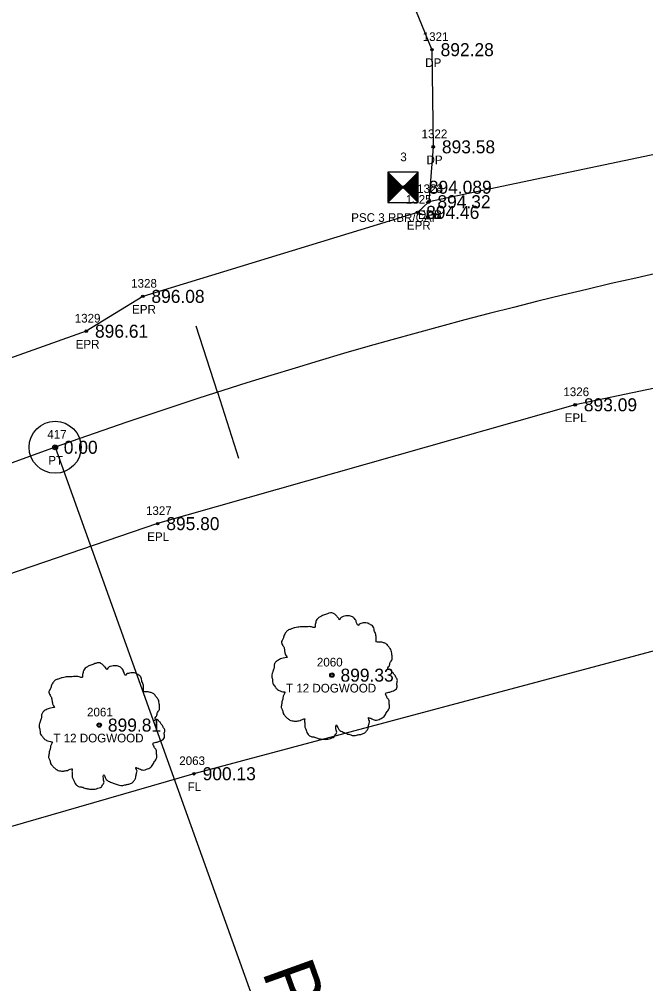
# Model space of a CAD drawing. Extents: x 1448136 to 1453623, y 1125056 to 1128842.
# Drawn here: x 1448926.9 to 1448999.1, y 1126836.9 to 1126948.2 of the extents above; entities that cross this region are included whole.
import ezdxf

# ---------------------------------------------------------------- set-up
doc = ezdxf.new("R2010")
doc.units = 0
for name, color, linetype in [('RD_EX_Driveway', 7, 'Continuous'), ('RD_EX_Driveway_txCode', 7, 'Continuous'), ('RD_EX_Fence_Other', 7, 'Continuous'), ('RD_EX_Fence_Other_txCode', 7, 'Continuous'), ('RD_EX_Road', 7, 'Continuous'), ('RD_EX_Road_txCode', 7, 'Continuous'), ('RD_EX_TX_Driveway_ELEV', 7, 'Continuous'), ('RD_EX_TX_Fence_Other_ELEV', 7, 'Continuous'), ('RD_EX_TX_Road_ELEV', 7, 'Continuous'), ('RD_EX_TX_VEG_ELEV', 7, 'Continuous'), ('RD_EX_VEG', 7, 'Continuous'), ('RD_EX_VEG_txCode', 7, 'Continuous'), ('RD_HC_Cl', 7, 'Continuous'), ('RD_HC_Data', 7, 'Continuous'), ('RD_HC_Data_Tic', 7, 'Continuous'), ('RD_HC_Survey', 7, 'Continuous'), ('RD_HC_Survey_ELEV', 7, 'Continuous'), ('RD_HC_txCode', 7, 'Continuous'), ('RD_SMD_Locator', 7, 'Continuous')]:
    doc.layers.add(name, color=color, linetype=linetype)

msp = doc.modelspace()

# ---------------------------------------------------------------- linework, layer by layer
at = {"layer": 'RD_EX_Driveway'}
msp.add_lwpolyline([(1449023.03, 1126937.4), (1449000.91, 1126949.09), (1448977.52, 1126965.39), (1448969.14, 1126957.73), (1448974.48, 1126944.7), (1448974.63, 1126933.49), (1448974.11, 1126927.16)], dxfattribs=at)
at = {"layer": 'RD_EX_Fence_Other'}
msp.add_lwpolyline([(1448975.76, 1126805.4), (1449010.37, 1126832.06), (1449003.73, 1126876.29), (1448947.02, 1126861.17), (1448899.19, 1126847.35), (1448908.83, 1126812.34)], dxfattribs=at)
at = {"layer": 'RD_EX_Road'}
for points in [[(1449482.54, 1126860.68), (1449432.31, 1126877.02), (1449388.08, 1126891.1), (1449338.36, 1126907.04), (1449288.58, 1126921), (1449240.68, 1126932.6), (1449188.86, 1126940.12), (1449140.06, 1126943.48), (1449087.15, 1126942.31), (1449035.96, 1126936.97), (1449031.74, 1126936.28), (1449027.6, 1126937.81), (1449023.03, 1126937.4), (1448974.11, 1126927.16), (1448972.81, 1126925.93), (1448941.11, 1126916.24), (1448934.6, 1126912.22), (1448888.05, 1126895.64)], [(1449474.36, 1126838.35), (1449426.72, 1126853.6), (1449379.49, 1126868.74), (1449332.07, 1126883.87), (1449284.48, 1126897.19), (1449236.53, 1126909.1), (1449187.55, 1126916.77), (1449138.32, 1126919.77), (1449088.85, 1126918.94), (1449039.71, 1126913.91), (1448991.01, 1126903.73), (1448942.83, 1126890.02), (1448896.24, 1126874.12)]]:
    msp.add_lwpolyline(points, dxfattribs=at)
at = {"layer": 'RD_EX_VEG'}
for centre, radius in [((1448962.93, 1126872.54), 0.25), ((1448962.92, 1126872.52), 0.0001), ((1448936.09, 1126866.78), 0.25), ((1448936.08, 1126866.76), 0.0001)]:
    msp.add_circle(centre, radius, dxfattribs=at)
for points in [[(1448963.06, 1126879.71), (1448962.76, 1126879.73), (1448962.44, 1126879.63), (1448962.19, 1126879.53), (1448961.96, 1126879.46), (1448961.74, 1126879.36), (1448961.44, 1126879.18), (1448961.21, 1126878.98), (1448961.09, 1126878.73), (1448961.04, 1126878.51), (1448960.99, 1126878.23), (1448960.99, 1126878.06), (1448960.86, 1126878.03), (1448960.71, 1126878.06), (1448960.46, 1126878.13), (1448960.21, 1126878.13), (1448959.96, 1126878.13), (1448959.61, 1126878.11), (1448959.26, 1126878.11), (1448958.99, 1126878.06), (1448958.66, 1126878.01), (1448958.29, 1126877.88), (1448957.94, 1126877.76), (1448957.64, 1126877.51), (1448957.39, 1126877.03), (1448957.27, 1126876.68), (1448957.12, 1126876.43), (1448957.27, 1126875.98), (1448957.44, 1126875.63), (1448957.47, 1126875.43), (1448957.54, 1126875.01), (1448957.64, 1126874.78), (1448957.77, 1126874.58), (1448957.69, 1126874.56), (1448957.32, 1126874.51), (1448957.02, 1126874.41), (1448956.59, 1126874.18), (1448956.37, 1126873.96), (1448956.27, 1126873.63), (1448956.24, 1126873.28), (1448956.14, 1126873.08), (1448956.07, 1126872.81), (1448956.04, 1126872.73), (1448955.99, 1126872.41), (1448956.09, 1126871.96), (1448956.12, 1126871.61), (1448956.24, 1126871.38), (1448956.39, 1126871.21), (1448956.57, 1126870.96), (1448956.97, 1126870.73), (1448957.29, 1126870.63), (1448957.49, 1126870.61), (1448957.32, 1126870.11), (1448957.27, 1126869.76), (1448957.14, 1126869.36), (1448957.14, 1126869.28), (1448957.09, 1126868.81), (1448957.24, 1126868.48), (1448957.32, 1126868.11), (1448957.49, 1126867.89), (1448957.77, 1126867.59), (1448958.09, 1126867.36), (1448958.59, 1126867.24), (1448958.99, 1126867.26), (1448959.56, 1126867.44), (1448959.81, 1126867.51), (1448959.79, 1126867.34), (1448959.81, 1126866.96), (1448959.81, 1126866.54), (1448959.96, 1126866.21), (1448960.06, 1126865.94), (1448960.21, 1126865.69), (1448960.54, 1126865.46), (1448960.94, 1126865.39), (1448961.36, 1126865.24), (1448961.81, 1126865.16), (1448962.31, 1126865.14), (1448962.91, 1126865.29), (1448963.19, 1126865.41), (1448963.29, 1126865.59), (1448963.49, 1126865.96), (1448963.44, 1126866.19), (1448963.46, 1126866.79), (1448963.56, 1126866.61), (1448963.74, 1126866.26), (1448964.24, 1126865.96), (1448964.64, 1126865.79), (1448965.11, 1126865.64), (1448965.41, 1126865.56), (1448965.89, 1126865.64), (1448966.26, 1126865.71), (1448966.64, 1126865.84), (1448966.94, 1126866.11), (1448967.11, 1126866.39), (1448967.16, 1126866.66), (1448967.24, 1126867.04), (1448967.29, 1126867.21)], [(1448967.29, 1126867.21), (1448967.21, 1126867.39), (1448967.16, 1126867.64), (1448967.24, 1126867.61), (1448967.41, 1126867.56), (1448967.69, 1126867.44), (1448967.91, 1126867.36), (1448968.24, 1126867.39), (1448968.51, 1126867.49), (1448968.96, 1126867.76), (1448969.24, 1126868.24), (1448969.51, 1126868.63), (1448969.59, 1126868.96), (1448969.54, 1126869.18), (1448969.51, 1126869.68), (1448969.31, 1126869.93), (1448969.26, 1126870.06), (1448969.16, 1126870.46), (1448969.24, 1126870.51), (1448969.51, 1126870.56), (1448969.89, 1126870.68), (1448970.16, 1126870.81), (1448970.38, 1126870.98), (1448970.46, 1126871.21), (1448970.43, 1126871.61), (1448970.48, 1126872.01), (1448970.41, 1126872.16), (1448970.31, 1126872.31), (1448970.23, 1126872.51), (1448970.08, 1126872.66), (1448969.99, 1126872.81), (1448969.89, 1126872.91), (1448969.76, 1126873.06), (1448969.59, 1126873.18), (1448969.44, 1126873.23), (1448969.39, 1126873.38), (1448969.54, 1126873.58), (1448969.59, 1126873.68), (1448969.61, 1126873.91), (1448969.84, 1126874.26), (1448969.89, 1126874.66), (1448969.84, 1126875.08), (1448969.79, 1126875.36), (1448969.64, 1126875.63), (1448969.44, 1126875.88), (1448969.31, 1126876.06), (1448969.14, 1126876.18), (1448968.81, 1126876.31), (1448968.56, 1126876.36), (1448968.21, 1126876.36), (1448968.01, 1126876.41), (1448968.04, 1126876.46), (1448968.04, 1126876.61), (1448968.04, 1126876.88), (1448967.96, 1126877.33), (1448967.81, 1126877.83), (1448967.81, 1126877.86), (1448967.71, 1126878.11), (1448967.49, 1126878.31), (1448967.31, 1126878.41), (1448967.11, 1126878.53), (1448966.86, 1126878.56), (1448966.56, 1126878.56), (1448966.29, 1126878.51), (1448966.09, 1126878.41), (1448965.91, 1126878.28), (1448965.84, 1126878.43), (1448965.74, 1126878.73), (1448965.69, 1126878.88), (1448965.54, 1126879.06), (1448965.31, 1126879.26), (1448964.86, 1126879.38), (1448964.24, 1126879.31), (1448963.94, 1126879.11), (1448963.79, 1126878.93), (1448963.74, 1126879.06), (1448963.54, 1126879.26), (1448963.44, 1126879.43), (1448963.26, 1126879.56), (1448963.11, 1126879.66), (1448963.01, 1126879.71)], [(1448936.23, 1126873.95), (1448935.93, 1126873.97), (1448935.6, 1126873.87), (1448935.35, 1126873.77), (1448935.13, 1126873.7), (1448934.9, 1126873.6), (1448934.6, 1126873.42), (1448934.38, 1126873.22), (1448934.25, 1126872.97), (1448934.2, 1126872.75), (1448934.15, 1126872.47), (1448934.15, 1126872.3), (1448934.03, 1126872.27), (1448933.88, 1126872.3), (1448933.63, 1126872.37), (1448933.38, 1126872.37), (1448933.13, 1126872.37), (1448932.78, 1126872.35), (1448932.43, 1126872.35), (1448932.15, 1126872.3), (1448931.83, 1126872.25), (1448931.45, 1126872.12), (1448931.1, 1126872), (1448930.8, 1126871.75), (1448930.55, 1126871.27), (1448930.43, 1126870.92), (1448930.28, 1126870.67), (1448930.43, 1126870.22), (1448930.6, 1126869.87), (1448930.63, 1126869.67), (1448930.7, 1126869.25), (1448930.8, 1126869.02), (1448930.93, 1126868.82), (1448930.85, 1126868.8), (1448930.48, 1126868.75), (1448930.18, 1126868.65), (1448929.75, 1126868.42), (1448929.53, 1126868.2), (1448929.43, 1126867.87), (1448929.4, 1126867.52), (1448929.3, 1126867.32), (1448929.23, 1126867.05), (1448929.2, 1126866.97), (1448929.15, 1126866.65), (1448929.25, 1126866.2), (1448929.28, 1126865.85), (1448929.4, 1126865.62), (1448929.55, 1126865.45), (1448929.73, 1126865.2), (1448930.13, 1126864.97), (1448930.45, 1126864.87), (1448930.65, 1126864.85), (1448930.48, 1126864.35), (1448930.43, 1126864), (1448930.3, 1126863.6), (1448930.3, 1126863.52), (1448930.25, 1126863.05), (1448930.4, 1126862.72), (1448930.48, 1126862.35), (1448930.65, 1126862.13), (1448930.93, 1126861.83), (1448931.25, 1126861.6), (1448931.75, 1126861.48), (1448932.15, 1126861.5), (1448932.73, 1126861.68), (1448932.98, 1126861.75), (1448932.95, 1126861.58), (1448932.98, 1126861.2), (1448932.98, 1126860.78), (1448933.13, 1126860.45), (1448933.23, 1126860.18), (1448933.38, 1126859.93), (1448933.7, 1126859.7), (1448934.1, 1126859.63), (1448934.53, 1126859.48), (1448934.98, 1126859.4), (1448935.48, 1126859.38), (1448936.08, 1126859.53), (1448936.35, 1126859.65), (1448936.45, 1126859.83), (1448936.65, 1126860.2), (1448936.6, 1126860.43), (1448936.63, 1126861.03), (1448936.73, 1126860.85), (1448936.9, 1126860.5), (1448937.4, 1126860.2), (1448937.8, 1126860.03), (1448938.27, 1126859.88), (1448938.57, 1126859.8), (1448939.05, 1126859.88), (1448939.42, 1126859.95), (1448939.8, 1126860.08), (1448940.1, 1126860.35), (1448940.27, 1126860.63), (1448940.32, 1126860.9), (1448940.4, 1126861.28), (1448940.45, 1126861.45)], [(1448940.45, 1126861.45), (1448940.37, 1126861.63), (1448940.32, 1126861.88), (1448940.4, 1126861.85), (1448940.57, 1126861.8), (1448940.85, 1126861.68), (1448941.07, 1126861.6), (1448941.4, 1126861.63), (1448941.67, 1126861.73), (1448942.12, 1126862), (1448942.4, 1126862.48), (1448942.67, 1126862.87), (1448942.75, 1126863.2), (1448942.7, 1126863.42), (1448942.67, 1126863.92), (1448942.47, 1126864.17), (1448942.42, 1126864.3), (1448942.32, 1126864.7), (1448942.4, 1126864.75), (1448942.67, 1126864.8), (1448943.05, 1126864.92), (1448943.32, 1126865.05), (1448943.55, 1126865.22), (1448943.62, 1126865.45), (1448943.6, 1126865.85), (1448943.65, 1126866.25), (1448943.57, 1126866.4), (1448943.47, 1126866.55), (1448943.4, 1126866.75), (1448943.25, 1126866.9), (1448943.15, 1126867.05), (1448943.05, 1126867.15), (1448942.92, 1126867.3), (1448942.75, 1126867.42), (1448942.6, 1126867.47), (1448942.55, 1126867.62), (1448942.7, 1126867.82), (1448942.75, 1126867.92), (1448942.77, 1126868.15), (1448943, 1126868.5), (1448943.05, 1126868.9), (1448943, 1126869.32), (1448942.95, 1126869.6), (1448942.8, 1126869.87), (1448942.6, 1126870.12), (1448942.47, 1126870.3), (1448942.3, 1126870.42), (1448941.97, 1126870.55), (1448941.72, 1126870.6), (1448941.37, 1126870.6), (1448941.17, 1126870.65), (1448941.2, 1126870.7), (1448941.2, 1126870.85), (1448941.2, 1126871.12), (1448941.12, 1126871.57), (1448940.97, 1126872.07), (1448940.97, 1126872.1), (1448940.87, 1126872.35), (1448940.65, 1126872.55), (1448940.47, 1126872.65), (1448940.27, 1126872.77), (1448940.02, 1126872.8), (1448939.72, 1126872.8), (1448939.45, 1126872.75), (1448939.25, 1126872.65), (1448939.07, 1126872.52), (1448939, 1126872.67), (1448938.9, 1126872.97), (1448938.85, 1126873.12), (1448938.7, 1126873.3), (1448938.47, 1126873.5), (1448938.02, 1126873.62), (1448937.4, 1126873.55), (1448937.1, 1126873.35), (1448936.95, 1126873.17), (1448936.9, 1126873.3), (1448936.7, 1126873.5), (1448936.6, 1126873.67), (1448936.43, 1126873.8), (1448936.28, 1126873.9), (1448936.18, 1126873.95)]]:
    msp.add_spline(points, degree=3, dxfattribs=at)
at = {"layer": 'RD_HC_Cl'}
msp.add_line((1448931, 1126898.83), (1448763.03, 1126838.55), dxfattribs=at)
msp.add_arc((1449124.53, 1126359.54), 572.96, 72.66042, 109.74133, dxfattribs=at)
at = {"layer": 'RD_HC_Data'}
msp.add_line((1448931, 1126898.83), (1448971.66, 1126785.54), dxfattribs=at)
for radius in [3, 0.282]:
    msp.add_circle((1448931, 1126898.83), radius, dxfattribs=at)
at = {"layer": 'RD_HC_Data_Tic'}
for q in [(1448947.28, 1126912.8), (1448952.16, 1126897.56)]:
    msp.add_line((1448949.72, 1126905.18), q, dxfattribs=at)
at = {"layer": 'RD_HC_Survey'}
for p, q in [((1448969.37, 1126930.58), (1448972.87, 1126927.08)), ((1448972.87, 1126930.58), (1448969.37, 1126927.08)), ((1448969.39, 1126930.56), (1448969.39, 1126927.11)), ((1448969.42, 1126930.53), (1448969.42, 1126927.13)), ((1448969.44, 1126930.51), (1448969.44, 1126927.16)), ((1448969.46, 1126930.48), (1448969.46, 1126927.18)), ((1448969.49, 1126930.46), (1448969.49, 1126927.21)), ((1448969.51, 1126930.43), (1448969.51, 1126927.23)), ((1448969.54, 1126930.41), (1448969.54, 1126927.26)), ((1448969.56, 1126930.39), (1448969.56, 1126927.28)), ((1448969.59, 1126930.36), (1448969.59, 1126927.31)), ((1448969.61, 1126930.34), (1448969.61, 1126927.33)), ((1448969.64, 1126930.31), (1448969.64, 1126927.36)), ((1448969.66, 1126930.29), (1448969.66, 1126927.38)), ((1448969.69, 1126930.26), (1448969.69, 1126927.4)), ((1448969.71, 1126930.24), (1448969.71, 1126927.43)), ((1448969.74, 1126930.21), (1448969.74, 1126927.45)), ((1448969.76, 1126930.19), (1448969.76, 1126927.48)), ((1448969.79, 1126930.16), (1448969.79, 1126927.5)), ((1448969.81, 1126930.14), (1448969.81, 1126927.53)), ((1448969.84, 1126930.11), (1448969.84, 1126927.55)), ((1448969.86, 1126930.09), (1448969.86, 1126927.58)), ((1448969.89, 1126930.06), (1448969.89, 1126927.6)), ((1448969.91, 1126930.04), (1448969.91, 1126927.63)), ((1448969.93, 1126930.01), (1448969.93, 1126927.65)), ((1448969.96, 1126929.99), (1448969.96, 1126927.68)), ((1448969.98, 1126929.96), (1448969.98, 1126927.7)), ((1448970.01, 1126929.94), (1448970.01, 1126927.73)), ((1448970.03, 1126929.91), (1448970.03, 1126927.75)), ((1448970.06, 1126929.89), (1448970.06, 1126927.78)), ((1448970.08, 1126929.87), (1448970.08, 1126927.8)), ((1448970.11, 1126929.84), (1448970.11, 1126927.83)), ((1448970.13, 1126929.82), (1448970.13, 1126927.85)), ((1448970.16, 1126929.79), (1448970.16, 1126927.88)), ((1448970.18, 1126929.77), (1448970.18, 1126927.9)), ((1448970.21, 1126929.74), (1448970.21, 1126927.92)), ((1448970.23, 1126929.72), (1448970.23, 1126927.95)), ((1448970.26, 1126929.69), (1448970.26, 1126927.97)), ((1448970.28, 1126929.67), (1448970.28, 1126928)), ((1448970.31, 1126929.64), (1448970.31, 1126928.02)), ((1448970.33, 1126929.62), (1448970.33, 1126928.05)), ((1448970.36, 1126929.59), (1448970.36, 1126928.07)), ((1448970.38, 1126929.57), (1448970.38, 1126928.1)), ((1448970.41, 1126929.54), (1448970.41, 1126928.12)), ((1448970.43, 1126929.52), (1448970.43, 1126928.15)), ((1448970.45, 1126929.49), (1448970.45, 1126928.17)), ((1448970.48, 1126929.47), (1448970.48, 1126928.2)), ((1448971.75, 1126929.47), (1448971.75, 1126928.2)), ((1448971.78, 1126929.49), (1448971.78, 1126928.17)), ((1448971.8, 1126929.52), (1448971.8, 1126928.15)), ((1448971.83, 1126929.54), (1448971.83, 1126928.12)), ((1448971.85, 1126929.57), (1448971.85, 1126928.1)), ((1448971.88, 1126929.59), (1448971.88, 1126928.07)), ((1448971.9, 1126929.62), (1448971.9, 1126928.05)), ((1448971.93, 1126929.64), (1448971.93, 1126928.02)), ((1448971.95, 1126929.67), (1448971.95, 1126928)), ((1448971.97, 1126929.69), (1448971.97, 1126927.97)), ((1448972, 1126929.72), (1448972, 1126927.95)), ((1448972.02, 1126929.74), (1448972.02, 1126927.92)), ((1448972.05, 1126929.77), (1448972.05, 1126927.9)), ((1448972.07, 1126929.79), (1448972.07, 1126927.88)), ((1448972.1, 1126929.82), (1448972.1, 1126927.85)), ((1448972.12, 1126929.84), (1448972.12, 1126927.83)), ((1448972.15, 1126929.87), (1448972.15, 1126927.8)), ((1448972.17, 1126929.89), (1448972.17, 1126927.78)), ((1448972.2, 1126929.91), (1448972.2, 1126927.75)), ((1448972.22, 1126929.94), (1448972.22, 1126927.73)), ((1448972.25, 1126929.96), (1448972.25, 1126927.7)), ((1448972.27, 1126929.99), (1448972.27, 1126927.68)), ((1448972.3, 1126930.01), (1448972.3, 1126927.65)), ((1448972.32, 1126930.04), (1448972.32, 1126927.63)), ((1448972.35, 1126930.06), (1448972.35, 1126927.6)), ((1448972.37, 1126930.09), (1448972.37, 1126927.58)), ((1448972.4, 1126930.11), (1448972.4, 1126927.55)), ((1448972.42, 1126930.14), (1448972.42, 1126927.53)), ((1448972.44, 1126930.16), (1448972.44, 1126927.5)), ((1448972.47, 1126930.19), (1448972.47, 1126927.48)), ((1448972.49, 1126930.21), (1448972.49, 1126927.45)), ((1448972.52, 1126930.24), (1448972.52, 1126927.43)), ((1448972.54, 1126930.26), (1448972.54, 1126927.4)), ((1448972.57, 1126930.29), (1448972.57, 1126927.38)), ((1448972.59, 1126930.31), (1448972.59, 1126927.36)), ((1448972.62, 1126930.34), (1448972.62, 1126927.33)), ((1448972.64, 1126930.36), (1448972.64, 1126927.31)), ((1448972.67, 1126930.39), (1448972.67, 1126927.28)), ((1448972.69, 1126930.41), (1448972.69, 1126927.26)), ((1448972.72, 1126930.43), (1448972.72, 1126927.23)), ((1448972.74, 1126930.46), (1448972.74, 1126927.21)), ((1448972.77, 1126930.48), (1448972.77, 1126927.18)), ((1448972.79, 1126930.51), (1448972.79, 1126927.16)), ((1448972.82, 1126930.53), (1448972.82, 1126927.13)), ((1448972.84, 1126930.56), (1448972.84, 1126927.11)), ((1448970.5, 1126929.44), (1448970.5, 1126928.22)), ((1448970.53, 1126929.42), (1448970.53, 1126928.25)), ((1448970.55, 1126929.4), (1448970.55, 1126928.27)), ((1448970.58, 1126929.37), (1448970.58, 1126928.3)), ((1448970.6, 1126929.35), (1448970.6, 1126928.32)), ((1448970.63, 1126929.32), (1448970.63, 1126928.35)), ((1448970.65, 1126929.3), (1448970.65, 1126928.37)), ((1448970.68, 1126929.27), (1448970.68, 1126928.39)), ((1448970.7, 1126929.25), (1448970.7, 1126928.42)), ((1448970.73, 1126929.22), (1448970.73, 1126928.44)), ((1448970.75, 1126929.2), (1448970.75, 1126928.47)), ((1448970.78, 1126929.17), (1448970.78, 1126928.49)), ((1448970.8, 1126929.15), (1448970.8, 1126928.52)), ((1448970.83, 1126929.12), (1448970.83, 1126928.54)), ((1448970.85, 1126929.1), (1448970.85, 1126928.57)), ((1448970.88, 1126929.07), (1448970.88, 1126928.59)), ((1448970.9, 1126929.05), (1448970.9, 1126928.62)), ((1448970.92, 1126929.02), (1448970.92, 1126928.64)), ((1448970.95, 1126929), (1448970.95, 1126928.67)), ((1448970.97, 1126928.97), (1448970.97, 1126928.69)), ((1448971, 1126928.95), (1448971, 1126928.72)), ((1448971.02, 1126928.93), (1448971.02, 1126928.74)), ((1448971.05, 1126928.9), (1448971.05, 1126928.77)), ((1448971.07, 1126928.88), (1448971.07, 1126928.79)), ((1448971.1, 1126928.85), (1448971.1, 1126928.82)), ((1448971.13, 1126928.85), (1448971.13, 1126928.82)), ((1448971.16, 1126928.88), (1448971.16, 1126928.79)), ((1448971.18, 1126928.9), (1448971.18, 1126928.77)), ((1448971.21, 1126928.93), (1448971.21, 1126928.74)), ((1448971.23, 1126928.95), (1448971.23, 1126928.72)), ((1448971.26, 1126928.97), (1448971.26, 1126928.69)), ((1448971.28, 1126929), (1448971.28, 1126928.67)), ((1448971.31, 1126929.02), (1448971.31, 1126928.64)), ((1448971.33, 1126929.05), (1448971.33, 1126928.62)), ((1448971.36, 1126929.07), (1448971.36, 1126928.59)), ((1448971.38, 1126929.1), (1448971.38, 1126928.57)), ((1448971.41, 1126929.12), (1448971.41, 1126928.54)), ((1448971.43, 1126929.15), (1448971.43, 1126928.52)), ((1448971.46, 1126929.17), (1448971.46, 1126928.49)), ((1448971.48, 1126929.2), (1448971.48, 1126928.47)), ((1448971.5, 1126929.22), (1448971.5, 1126928.44)), ((1448971.53, 1126929.25), (1448971.53, 1126928.42)), ((1448971.55, 1126929.27), (1448971.55, 1126928.39)), ((1448971.58, 1126929.3), (1448971.58, 1126928.37)), ((1448971.6, 1126929.32), (1448971.6, 1126928.35)), ((1448971.63, 1126929.35), (1448971.63, 1126928.32)), ((1448971.65, 1126929.37), (1448971.65, 1126928.3)), ((1448971.68, 1126929.4), (1448971.68, 1126928.27)), ((1448971.7, 1126929.42), (1448971.7, 1126928.25)), ((1448971.73, 1126929.44), (1448971.73, 1126928.22))]:
    msp.add_line(p, q, dxfattribs=at)
msp.add_lwpolyline([(1448972.87, 1126930.58), (1448969.37, 1126930.58), (1448969.37, 1126927.08), (1448972.87, 1126927.08)], close=True, dxfattribs=at)
at = {"layer": 'RD_SMD_Locator'}
for centre in [(1448974.48, 1126944.7), (1448974.63, 1126933.49), (1448971.12, 1126928.83), (1448974.11, 1126927.16), (1448974.11, 1126927.16), (1448972.81, 1126925.93), (1448941.11, 1126916.24), (1448934.6, 1126912.22), (1448991.01, 1126903.73), (1448931, 1126898.83), (1448942.83, 1126890.02), (1448962.93, 1126872.54), (1448936.09, 1126866.78), (1448947.02, 1126861.17)]:
    msp.add_circle(centre, 0.15, dxfattribs=at)

# ---------------------------------------------------------------- texts
at = {"layer": 'RD_EX_Driveway_txCode'}
for s, p in [('1321', (1448973.41, 1126945.7)), ('DP', (1448973.7, 1126942.7)), ('1322', (1448973.28, 1126934.49)), ('DP', (1448973.85, 1126931.49)), ('1324', (1448972.77, 1126928.16)), ('DPB', (1448972.86, 1126925.16))]:
    msp.add_text(s, height=1, dxfattribs=at).set_placement(p)
at = {"layer": 'RD_EX_Fence_Other_txCode'}
for s, p in [('2063', (1448945.32, 1126862.17)), ('FL', (1448946.28, 1126859.17))]:
    msp.add_text(s, height=1, dxfattribs=at).set_placement(p)
at = {"layer": 'RD_EX_Road_txCode'}
for s, p in [('1323', (1448972.77, 1126928.16)), ('1325', (1448971.46, 1126926.93)), ('EPR', (1448972.88, 1126925.16)), ('EPR', (1448971.58, 1126923.93)), ('1328', (1448939.77, 1126917.24)), ('EPR', (1448939.88, 1126914.24)), ('1329', (1448933.26, 1126913.22)), ('EPR', (1448933.37, 1126910.22)), ('1326', (1448989.64, 1126904.73)), ('EPL', (1448989.8, 1126901.73)), ('1327', (1448941.48, 1126891.02)), ('EPL', (1448941.62, 1126888.02))]:
    msp.add_text(s, height=1, dxfattribs=at).set_placement(p)
at = {"layer": 'RD_EX_TX_Driveway_ELEV'}
for s, p in [('892.28', (1448975.48, 1126943.95)), ('893.58', (1448975.63, 1126932.74)), ('894.32', (1448975.11, 1126926.41))]:
    msp.add_text(s, height=1.5, dxfattribs=at).set_placement(p)
at = {"layer": 'RD_EX_TX_Fence_Other_ELEV'}
msp.add_text('900.13', height=1.5, dxfattribs=at).set_placement((1448948.02, 1126860.42))
at = {"layer": 'RD_EX_TX_Road_ELEV'}
for s, p in [('894.32', (1448975.11, 1126926.41)), ('894.46', (1448973.81, 1126925.18)), ('896.08', (1448942.11, 1126915.49)), ('896.61', (1448935.6, 1126911.47)), ('893.09', (1448992.01, 1126902.98)), ('895.80', (1448943.83, 1126889.27))]:
    msp.add_text(s, height=1.5, dxfattribs=at).set_placement(p)
at = {"layer": 'RD_EX_TX_VEG_ELEV'}
for s, p in [('899.33', (1448963.93, 1126871.79)), ('899.81', (1448937.09, 1126866.03))]:
    msp.add_text(s, height=1.5, dxfattribs=at).set_placement(p)
at = {"layer": 'RD_EX_VEG_txCode'}
for s, p in [('2060', (1448961.2, 1126873.54)), ('T 12 DOGWOOD', (1448957.64, 1126870.54)), ('2061', (1448934.68, 1126867.78)), ('T 12 DOGWOOD', (1448930.8, 1126864.78))]:
    msp.add_text(s, height=1, dxfattribs=at).set_placement(p)
at = {"layer": 'RD_HC_Data'}
msp.add_text('PT=395+19.77', height=6, rotation=289.7413, dxfattribs=at).set_placement((1448954.84, 1126838.32))
at = {"layer": 'RD_HC_Survey_ELEV'}
for s, p in [('894.089', (1448974.12, 1126928.08)), ('0.00', (1448932, 1126898.08))]:
    msp.add_text(s, height=1.5, dxfattribs=at).set_placement(p)
at = {"layer": 'RD_HC_txCode'}
for s, p in [('3', (1448970.83, 1126931.83)), ('PSC 3 RBR/CAP', (1448965.16, 1126924.83)), ('417', (1448930.1, 1126899.83)), ('PT', (1448930.21, 1126896.83))]:
    msp.add_text(s, height=1, dxfattribs=at).set_placement(p)

doc.saveas('drawing.dxf')
